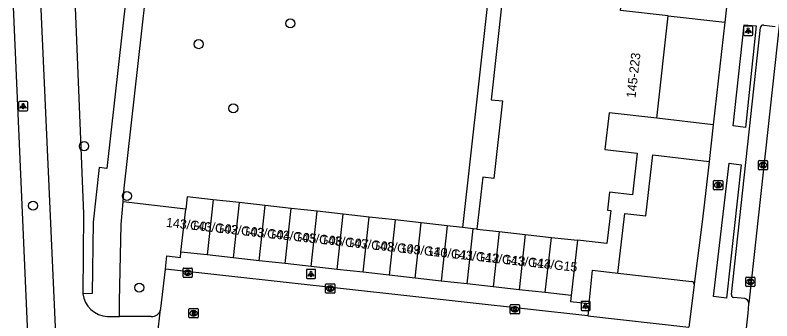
# Model space of a CAD drawing. Extents: x 161928 to 163055, y 386475 to 387428.
# Drawn here: x 161979 to 162060.7, y 386611.6 to 386644.6 of the extents above; entities that cross this region are included whole.
import ezdxf

# ---------------------------------------------------------------- set-up
doc = ezdxf.new("R2010")
doc.units = 0
for name, color, linetype in [('IMGEO_Boom', 7, 'Continuous'), ('IMGEO_Brandkraan', 7, 'Continuous'), ('IMGEO_Fietspad_gesloten', 7, 'Continuous'), ('IMGEO_Groenvoorziening', 7, 'Continuous'), ('IMGEO_Kolk', 7, 'Continuous'), ('IMGEO_Lichtpunt', 7, 'Continuous'), ('IMGEO_Pand', 7, 'Continuous'), ('IMGEO_Pand_nummerreeks', 7, 'Continuous'), ('IMGEO_Parkeervlak_open', 7, 'Continuous'), ('IMGEO_Rijbaan_lokaal_open', 7, 'Continuous'), ('IMGEO_Rijbaan_regionaal_gesloten', 7, 'Continuous'), ('IMGEO_Rioolput', 7, 'Continuous'), ('IMGEO_Voetpad_open', 7, 'Continuous')]:
    doc.layers.add(name, color=color, linetype=linetype)

msp = doc.modelspace()

# ---------------------------------------------------------------- linework, layer by layer
at = {"layer": 'IMGEO_Boom'}
for centre in [(162008.736, 386643.743), (161998.843, 386641.507), (162002.594, 386634.574), (161986.471, 386630.491), (161991.087, 386625.111), (161980.961, 386624.056), (161992.421, 386615.212)]:
    msp.add_circle(centre, 0.489, dxfattribs=at)
at = {"layer": 'IMGEO_Brandkraan'}
for p, q in [((162054.441, 386625.856), (162054.441, 386626.708)), ((162054.516, 386626.782), (162055.368, 386626.782)), ((162055.442, 386626.708), (162055.442, 386625.856)), ((162054.952, 386626.002), (162054.927, 386626.002)), ((162054.929, 386626.562), (162054.954, 386626.562)), ((162055.368, 386625.782), (162054.516, 386625.782))]:
    msp.add_line(p, q, dxfattribs=at)
for points in [[(162054.441, 386625.856), (162054.441, 386626.708)], [(162054.516, 386626.782), (162055.368, 386626.782)], [(162055.442, 386626.708), (162055.442, 386625.856)], [(162054.789, 386626.482), (162054.789, 386626.082), (162055.002, 386626.082)], [(162055.02, 386626.482), (162054.789, 386626.482)], [(162054.968, 386626.401), (162054.914, 386626.401), (162054.914, 386626.325)], [(162054.914, 386626.325), (162054.967, 386626.325)], [(162054.976, 386626.249), (162054.914, 386626.249), (162054.914, 386626.168)], [(162054.914, 386626.168), (162054.976, 386626.168)], [(162055.368, 386625.782), (162054.516, 386625.782)]]:
    msp.add_lwpolyline(points, dxfattribs=at)
for centre, radius, start, end in [((162054.518, 386626.706), 0.0765, 91.55205, 178.44795), ((162054.518, 386626.706), 0.0765, 91.55205, 178.44795), ((162055.366, 386626.706), 0.0765, 1.55205, 88.44795), ((162055.366, 386626.706), 0.0765, 1.55205, 88.44795), ((162054.518, 386625.858), 0.0765, 181.55205, 268.44795), ((162054.518, 386625.858), 0.0765, 181.55205, 268.44795), ((162054.969, 386626.363), 0.0379, 267.82845, 90.93552), ((162054.977, 386626.208), 0.0404, 269.87594, 90.50774), ((162055.008, 386626.333), 0.251, 268.66757, 293.53466), ((162055.024, 386626.337), 0.145, 59.4692, 91.53667), ((162055.049, 386626.384), 0.0922, 285.51372, 58.15012), ((162055.054, 386626.192), 0.105, 301.31148, 78.98903), ((162055.366, 386625.858), 0.0765, 271.55205, 358.44795), ((162055.366, 386625.858), 0.0765, 271.55205, 358.44795)]:
    msp.add_arc(centre, radius, start, end, dxfattribs=at)
for centre, major_axis, ratio, start_param, end_param in [((162054.928, 386626.282), (-0.387, 0.002), 0.722429, 4.712389, 7.853982), ((162054.953, 386626.282), (-0.39, 0.002), 0.717154, 1.570796, 4.712389)]:
    msp.add_ellipse(centre, major_axis=major_axis, ratio=ratio, start_param=start_param, end_param=end_param, dxfattribs=at)
at = {"layer": 'IMGEO_Fietspad_gesloten'}
for points in [[(161984.736, 386580.648), (161979.611, 386694.81), (161979.277, 386701.082), (161979.827, 386719.32), (161980.765, 386731.703), (161982.714, 386750), (161987.259, 386790.761)], [(161982.763, 386700.414), (161982.834, 386697.131), (161985.017, 386657.078), (161986.078, 386631.198), (161986.407, 386623.174), (161986.323, 386614.553)], [(161988.988, 386612.104), (161990.289, 386612.098)], [(161993.706, 386612.082), (161990.289, 386612.098)]]:
    msp.add_lwpolyline(points, dxfattribs=at)
for centre, radius, start, end in [((161989.121, 386614.923), 2.822, 187.53195, 267.30518), ((161993.734, 386613.113), 1.032, 268.45682, 346.01003)]:
    msp.add_arc(centre, radius, start, end, dxfattribs=at)
at = {"layer": 'IMGEO_Groenvoorziening'}
for points in [[(162031.664, 386660.431), (162027.344, 386621.709)], [(161997.447, 386623.691), (161990.684, 386624.497)]]:
    msp.add_lwpolyline(points, dxfattribs=at)
at = {"layer": 'IMGEO_Kolk'}
for p, q in [((162059.295, 386628.019), (162059.295, 386628.871)), ((162059.37, 386628.945), (162060.222, 386628.945)), ((162059.783, 386628.725), (162059.808, 386628.725)), ((162060.296, 386628.871), (162060.296, 386628.019)), ((162060.222, 386627.945), (162059.37, 386627.945)), ((162059.806, 386628.165), (162059.781, 386628.165)), ((161997.151, 386616.4), (161997.151, 386617.252)), ((161997.226, 386617.326), (161998.078, 386617.326)), ((161997.639, 386617.106), (161997.664, 386617.106)), ((161998.152, 386617.252), (161998.152, 386616.4)), ((161998.078, 386616.326), (161997.226, 386616.326)), ((161997.662, 386616.546), (161997.637, 386616.546)), ((162057.925, 386615.421), (162057.925, 386616.273)), ((162058, 386616.347), (162058.852, 386616.347)), ((162058.413, 386616.127), (162058.438, 386616.127)), ((162058.926, 386616.273), (162058.926, 386615.421)), ((162012.552, 386614.691), (162012.552, 386615.543)), ((162012.627, 386615.617), (162013.479, 386615.617)), ((162013.04, 386615.397), (162013.065, 386615.397)), ((162013.553, 386615.543), (162013.553, 386614.691)), ((162058.852, 386615.347), (162058, 386615.347)), ((162058.436, 386615.567), (162058.411, 386615.567)), ((162013.479, 386614.617), (162012.627, 386614.617)), ((162013.063, 386614.837), (162013.038, 386614.837)), ((162032.49, 386612.452), (162032.49, 386613.304)), ((162032.565, 386613.378), (162033.417, 386613.378)), ((162032.978, 386613.158), (162033.003, 386613.158)), ((162033.491, 386613.304), (162033.491, 386612.452)), ((162033.417, 386612.378), (162032.565, 386612.378)), ((162033.001, 386612.598), (162032.976, 386612.598))]:
    msp.add_line(p, q, dxfattribs=at)
for points in [[(162059.295, 386628.019), (162059.295, 386628.871)], [(162059.37, 386628.945), (162060.222, 386628.945)], [(162059.616, 386628.645), (162059.739, 386628.645), (162059.739, 386628.494), (162059.869, 386628.645), (162060.033, 386628.645), (162059.887, 386628.494), (162060.04, 386628.245), (162059.888, 386628.245), (162059.803, 386628.409), (162059.739, 386628.342), (162059.739, 386628.245), (162059.616, 386628.245), (162059.616, 386628.645)], [(162060.296, 386628.871), (162060.296, 386628.019)], [(162060.222, 386627.945), (162059.37, 386627.945)], [(161997.151, 386616.4), (161997.151, 386617.252)], [(161997.226, 386617.326), (161998.078, 386617.326)], [(161997.472, 386617.026), (161997.595, 386617.026), (161997.595, 386616.875), (161997.725, 386617.026), (161997.889, 386617.026), (161997.743, 386616.875), (161997.896, 386616.626), (161997.744, 386616.626), (161997.659, 386616.79), (161997.595, 386616.723), (161997.595, 386616.626), (161997.472, 386616.626), (161997.472, 386617.026)], [(161998.152, 386617.252), (161998.152, 386616.4)], [(161998.078, 386616.326), (161997.226, 386616.326)], [(162057.925, 386615.421), (162057.925, 386616.273)], [(162058, 386616.347), (162058.852, 386616.347)], [(162058.246, 386616.047), (162058.369, 386616.047), (162058.369, 386615.896), (162058.499, 386616.047), (162058.663, 386616.047), (162058.517, 386615.896), (162058.67, 386615.647), (162058.518, 386615.647), (162058.433, 386615.811), (162058.369, 386615.744), (162058.369, 386615.647), (162058.246, 386615.647), (162058.246, 386616.047)], [(162058.926, 386616.273), (162058.926, 386615.421)], [(162012.552, 386614.691), (162012.552, 386615.543)], [(162012.627, 386615.617), (162013.479, 386615.617)], [(162012.873, 386615.317), (162012.996, 386615.317), (162012.996, 386615.166), (162013.126, 386615.317), (162013.29, 386615.317), (162013.144, 386615.166), (162013.297, 386614.917), (162013.145, 386614.917), (162013.06, 386615.081), (162012.996, 386615.014), (162012.996, 386614.917), (162012.873, 386614.917), (162012.873, 386615.317)], [(162013.553, 386615.543), (162013.553, 386614.691)], [(162058.852, 386615.347), (162058, 386615.347)], [(162013.479, 386614.617), (162012.627, 386614.617)], [(162032.49, 386612.452), (162032.49, 386613.304)], [(162032.565, 386613.378), (162033.417, 386613.378)], [(162032.811, 386613.078), (162032.934, 386613.078), (162032.934, 386612.927), (162033.064, 386613.078), (162033.228, 386613.078), (162033.082, 386612.927), (162033.235, 386612.678), (162033.083, 386612.678), (162032.998, 386612.842), (162032.934, 386612.775), (162032.934, 386612.678), (162032.811, 386612.678), (162032.811, 386613.078)], [(162033.491, 386613.304), (162033.491, 386612.452)], [(162033.417, 386612.378), (162032.565, 386612.378)]]:
    msp.add_lwpolyline(points, dxfattribs=at)
for centre, start, end in [((162059.372, 386628.869), 91.55205, 178.44795), ((162059.372, 386628.869), 91.55205, 178.44795), ((162060.22, 386628.869), 1.55205, 88.44795), ((162060.22, 386628.869), 1.55205, 88.44795), ((162059.372, 386628.021), 181.55205, 268.44795), ((162059.372, 386628.021), 181.55205, 268.44795), ((162060.22, 386628.021), 271.55205, 358.44795), ((162060.22, 386628.021), 271.55205, 358.44795), ((161997.228, 386617.25), 91.55205, 178.44795), ((161997.228, 386617.25), 91.55205, 178.44795), ((161998.076, 386617.25), 1.55205, 88.44795), ((161998.076, 386617.25), 1.55205, 88.44795), ((161997.228, 386616.402), 181.55205, 268.44795), ((161997.228, 386616.402), 181.55205, 268.44795), ((161998.076, 386616.402), 271.55205, 358.44795), ((161998.076, 386616.402), 271.55205, 358.44795), ((162058.002, 386616.271), 91.55205, 178.44795), ((162058.002, 386616.271), 91.55205, 178.44795), ((162058.85, 386616.271), 1.55205, 88.44795), ((162058.85, 386616.271), 1.55205, 88.44795), ((162012.629, 386615.541), 91.55205, 178.44795), ((162012.629, 386615.541), 91.55205, 178.44795), ((162013.477, 386615.541), 1.55205, 88.44795), ((162013.477, 386615.541), 1.55205, 88.44795), ((162058.002, 386615.423), 181.55205, 268.44795), ((162058.002, 386615.423), 181.55205, 268.44795), ((162058.85, 386615.423), 271.55205, 358.44795), ((162058.85, 386615.423), 271.55205, 358.44795), ((162012.629, 386614.693), 181.55205, 268.44795), ((162012.629, 386614.693), 181.55205, 268.44795), ((162013.477, 386614.693), 271.55205, 358.44795), ((162013.477, 386614.693), 271.55205, 358.44795), ((162032.567, 386613.302), 91.55205, 178.44795), ((162032.567, 386613.302), 91.55205, 178.44795), ((162033.415, 386613.302), 1.55205, 88.44795), ((162033.415, 386613.302), 1.55205, 88.44795), ((162032.567, 386612.454), 181.55205, 268.44795), ((162032.567, 386612.454), 181.55205, 268.44795), ((162033.415, 386612.454), 271.55205, 358.44795), ((162033.415, 386612.454), 271.55205, 358.44795)]:
    msp.add_arc(centre, 0.0765, start, end, dxfattribs=at)
for centre, major_axis, ratio, start_param, end_param in [((162059.782, 386628.445), (-0.387, 0.002), 0.722429, 4.712389, 7.853982), ((162059.807, 386628.445), (-0.39, 0.002), 0.717154, 1.570796, 4.712389), ((161997.638, 386616.826), (-0.387, 0.002), 0.722429, 4.712389, 7.853982), ((161997.663, 386616.826), (-0.39, 0.002), 0.717154, 1.570796, 4.712389), ((162058.412, 386615.847), (-0.387, 0.002), 0.722429, 4.712389, 7.853982), ((162058.437, 386615.847), (-0.39, 0.002), 0.717154, 1.570796, 4.712389), ((162013.039, 386615.117), (-0.387, 0.002), 0.722429, 4.712389, 7.853982), ((162013.064, 386615.117), (-0.39, 0.002), 0.717154, 1.570796, 4.712389), ((162032.977, 386612.878), (-0.387, 0.002), 0.722429, 4.712389, 7.853982), ((162033.002, 386612.878), (-0.39, 0.002), 0.717154, 1.570796, 4.712389)]:
    msp.add_ellipse(centre, major_axis=major_axis, ratio=ratio, start_param=start_param, end_param=end_param, dxfattribs=at)
at = {"layer": 'IMGEO_Lichtpunt'}
for p, q in [((162057.7, 386643.356), (162057.7, 386642.549)), ((162057.7, 386643.356), (162057.7, 386642.549)), ((162058.602, 386643.451), (162057.794, 386643.451)), ((162058.602, 386643.451), (162057.794, 386643.451)), ((162058.696, 386642.549), (162058.696, 386643.356)), ((162058.696, 386642.549), (162058.696, 386643.356)), ((162057.794, 386642.455), (162058.602, 386642.455)), ((162057.794, 386642.455), (162058.602, 386642.455)), ((161979.385, 386635.216), (161979.385, 386634.409)), ((161979.385, 386635.216), (161979.385, 386634.409)), ((161980.287, 386635.311), (161979.479, 386635.311)), ((161980.287, 386635.311), (161979.479, 386635.311)), ((161980.381, 386634.409), (161980.381, 386635.216)), ((161980.381, 386634.409), (161980.381, 386635.216)), ((161979.479, 386634.315), (161980.287, 386634.315)), ((161979.479, 386634.315), (161980.287, 386634.315)), ((162010.476, 386617.095), (162010.476, 386616.288)), ((162010.476, 386617.095), (162010.476, 386616.288)), ((162011.378, 386617.19), (162010.57, 386617.19)), ((162011.378, 386617.19), (162010.57, 386617.19)), ((162011.472, 386616.288), (162011.472, 386617.095)), ((162011.472, 386616.288), (162011.472, 386617.095)), ((162010.57, 386616.194), (162011.378, 386616.194)), ((162010.57, 386616.194), (162011.378, 386616.194)), ((162040.138, 386613.641), (162040.138, 386612.834)), ((162040.138, 386613.641), (162040.138, 386612.834)), ((162041.04, 386613.736), (162040.232, 386613.736)), ((162041.04, 386613.736), (162040.232, 386613.736)), ((162041.134, 386612.834), (162041.134, 386613.641)), ((162041.134, 386612.834), (162041.134, 386613.641)), ((162040.232, 386612.74), (162041.04, 386612.74)), ((162040.232, 386612.74), (162041.04, 386612.74))]:
    msp.add_line(p, q, dxfattribs=at)
for points in [[(162058.074, 386643.02), (162058.113, 386642.992), (162057.925, 386642.73), (162057.887, 386642.757), (162058.074, 386643.02)], [(162058.286, 386642.992), (162058.324, 386643.019), (162058.511, 386642.757), (162058.472, 386642.729), (162058.286, 386642.992)], [(162058.176, 386642.972), (162058.223, 386642.972), (162058.223, 386642.65), (162058.176, 386642.65), (162058.176, 386642.972)], [(161979.759, 386634.88), (161979.798, 386634.852), (161979.61, 386634.59), (161979.572, 386634.617), (161979.759, 386634.88)], [(161979.971, 386634.852), (161980.009, 386634.879), (161980.196, 386634.617), (161980.157, 386634.589), (161979.971, 386634.852)], [(161979.861, 386634.832), (161979.908, 386634.832), (161979.908, 386634.51), (161979.861, 386634.51), (161979.861, 386634.832)], [(162010.85, 386616.759), (162010.889, 386616.731), (162010.701, 386616.469), (162010.663, 386616.496), (162010.85, 386616.759)], [(162010.952, 386616.711), (162010.999, 386616.711), (162010.999, 386616.389), (162010.952, 386616.389), (162010.952, 386616.711)], [(162011.062, 386616.731), (162011.1, 386616.758), (162011.287, 386616.496), (162011.248, 386616.468), (162011.062, 386616.731)], [(162040.512, 386613.305), (162040.551, 386613.277), (162040.363, 386613.015), (162040.325, 386613.042), (162040.512, 386613.305)], [(162040.614, 386613.257), (162040.661, 386613.257), (162040.661, 386612.935), (162040.614, 386612.935), (162040.614, 386613.257)], [(162040.724, 386613.277), (162040.762, 386613.304), (162040.949, 386613.042), (162040.91, 386613.014), (162040.724, 386613.277)]]:
    msp.add_lwpolyline(points, dxfattribs=at)
for centre in [(162058.199, 386643.154), (161979.884, 386635.014), (162010.975, 386616.893), (162040.637, 386613.439)]:
    msp.add_circle(centre, 0.0994, dxfattribs=at)
for centre, start, end in [((162057.794, 386643.356), 90, 180), ((162057.794, 386643.356), 90, 180), ((162058.602, 386643.356), 0, 90), ((162058.602, 386643.356), 0, 90), ((162057.794, 386642.549), 180, 270), ((162057.794, 386642.549), 180, 270), ((162058.602, 386642.549), 270, 0), ((162058.602, 386642.549), 270, 360), ((161979.479, 386635.216), 90, 180), ((161979.479, 386635.216), 90, 180), ((161980.287, 386635.216), 0, 90), ((161980.287, 386635.216), 0, 90), ((161979.479, 386634.409), 180, 270), ((161979.479, 386634.409), 180, 270), ((161980.287, 386634.409), 270, 0), ((161980.287, 386634.409), 270, 360), ((162010.57, 386617.095), 90, 180), ((162010.57, 386617.095), 90, 180), ((162011.378, 386617.095), 0, 90), ((162011.378, 386617.095), 0, 90), ((162010.57, 386616.288), 180, 270), ((162010.57, 386616.288), 180, 270), ((162011.378, 386616.288), 270, 0), ((162011.378, 386616.288), 270, 360), ((162040.232, 386613.641), 90, 180), ((162040.232, 386613.641), 90, 180), ((162041.04, 386613.641), 0, 90), ((162041.04, 386613.641), 0, 90), ((162040.232, 386612.834), 180, 270), ((162040.232, 386612.834), 180, 270), ((162041.04, 386612.834), 270, 0), ((162041.04, 386612.834), 270, 360)]:
    msp.add_arc(centre, 0.0946, start, end, dxfattribs=at)
at = {"layer": 'IMGEO_Pand'}
for points in [[(162033.207, 386660.295), (162032.572, 386654.589), (162033.788, 386654.454), (162032.858, 386646.103), (162031.616, 386646.242), (162030.421, 386635.511), (162031.659, 386635.373), (162030.727, 386626.999), (162029.524, 386627.133), (162028.901, 386621.536)], [(162049.548, 386644.556), (162044.41, 386645.129), (162044.816, 386649.034), (162048.304, 386648.645)], [(162048.319, 386633.515), (162049.548, 386644.556)], [(162048.319, 386633.515), (162043.181, 386634.087), (162042.701, 386630.128), (162046.189, 386629.74), (162045.689, 386625.252), (162043.226, 386625.526), (162043.011, 386623.597), (162043.342, 386623.56), (162042.942, 386619.973), (162039.742, 386620.33)], [(162000.405, 386624.708), (161997.595, 386625.021), (161997.447, 386623.691)], [(162000.405, 386624.708), (161999.742, 386618.745)], [(162003.215, 386624.395), (162000.405, 386624.708)], [(162003.215, 386624.395), (162002.552, 386618.433)], [(162006.025, 386624.083), (162003.215, 386624.395)], [(161996.932, 386619.058), (161997.447, 386623.691)], [(162005.361, 386618.12), (162006.025, 386624.083)], [(162008.835, 386623.77), (162006.025, 386624.083)], [(162008.171, 386617.807), (162008.835, 386623.77)], [(162011.645, 386623.457), (162008.835, 386623.77)], [(162010.981, 386617.494), (162011.645, 386623.457)], [(162014.454, 386623.144), (162011.645, 386623.457)], [(162013.791, 386617.182), (162014.454, 386623.144)], [(162017.264, 386622.831), (162014.454, 386623.144)], [(162016.601, 386616.869), (162017.264, 386622.831)], [(162020.074, 386622.519), (162017.264, 386622.831)], [(162020.074, 386622.519), (162019.41, 386616.556)], [(162022.884, 386622.206), (162020.074, 386622.519)], [(162022.22, 386616.243), (162022.884, 386622.206)], [(162025.694, 386621.893), (162022.884, 386622.206)], [(162025.694, 386621.893), (162025.03, 386615.931)], [(162027.344, 386621.709), (162025.694, 386621.893)], [(162028.503, 386621.58), (162027.344, 386621.709)], [(162027.84, 386615.618), (162028.503, 386621.58)], [(162028.901, 386621.536), (162028.503, 386621.58)], [(162028.901, 386621.536), (162031.313, 386621.268)], [(162031.313, 386621.268), (162030.65, 386615.305)], [(162031.313, 386621.268), (162034.123, 386620.955)], [(162034.123, 386620.955), (162033.459, 386614.992)], [(162034.123, 386620.955), (162036.933, 386620.643)], [(162036.269, 386614.68), (162036.933, 386620.643)], [(162036.933, 386620.643), (162039.742, 386620.33)], [(162039.742, 386620.33), (162039.079, 386614.367)], [(161999.742, 386618.745), (161996.932, 386619.058)], [(162002.552, 386618.433), (161999.742, 386618.745)], [(162005.361, 386618.12), (162002.552, 386618.433)], [(162008.171, 386617.807), (162005.361, 386618.12)], [(162010.981, 386617.494), (162008.171, 386617.807)], [(162013.791, 386617.182), (162010.981, 386617.494)], [(162016.601, 386616.869), (162013.791, 386617.182)], [(162019.41, 386616.556), (162016.601, 386616.869)], [(162022.22, 386616.243), (162019.41, 386616.556)], [(162025.03, 386615.931), (162022.22, 386616.243)], [(162027.84, 386615.618), (162025.03, 386615.931)], [(162030.65, 386615.305), (162027.84, 386615.618)], [(162033.459, 386614.992), (162030.65, 386615.305)], [(162036.269, 386614.68), (162033.459, 386614.992)], [(162039.079, 386614.367), (162036.269, 386614.68)]]:
    msp.add_lwpolyline(points, dxfattribs=at)
at = {"layer": 'IMGEO_Parkeervlak_open'}
msp.add_lwpolyline([(162044.129, 386616.787), (162052.113, 386615.893)], dxfattribs=at)
msp.add_arc((162052.072, 386615.619), 0.277, 356.71692, 81.56, dxfattribs=at)
at = {"layer": 'IMGEO_Rijbaan_lokaal_open'}
for points in [[(162061.585, 386643.805), (162058.246, 386613.543)], [(161994.754, 386612.959), (161995.25, 386617.216)], [(162040.86, 386612.186), (161995.25, 386617.216)], [(161994.297, 386609.109), (161994.735, 386612.864)], [(162058.246, 386613.543), (162058.239, 386613.473), (162058.171, 386612.457), (162056.936, 386601.481), (162056.523, 386597.775), (162056.212, 386594.954)], [(162040.86, 386612.186), (162051.78, 386610.944)]]:
    msp.add_lwpolyline(points, dxfattribs=at)
msp.add_arc((161994.012, 386613.058), 0.749, 344.97984, 352.4003, dxfattribs=at)
at = {"layer": 'IMGEO_Rijbaan_regionaal_gesloten'}
msp.add_lwpolyline([(161981.679, 386580.648), (161976.551, 386697.302), (161974.502, 386742.455), (161974.558, 386746.864), (161974.908, 386750), (161979.57, 386791.732)], dxfattribs=at)
at = {"layer": 'IMGEO_Rioolput'}
for p, q in [((161997.792, 386612.03), (161997.792, 386612.882)), ((161997.867, 386612.956), (161998.719, 386612.956)), ((161998.793, 386612.882), (161998.793, 386612.03)), ((161998.303, 386612.176), (161998.278, 386612.176)), ((161998.28, 386612.736), (161998.305, 386612.736)), ((161998.719, 386611.956), (161997.867, 386611.956))]:
    msp.add_line(p, q, dxfattribs=at)
for points in [[(161997.792, 386612.03), (161997.792, 386612.882)], [(161997.867, 386612.956), (161998.719, 386612.956)], [(161998.793, 386612.882), (161998.793, 386612.03)], [(161998.381, 386612.654), (161998.129, 386612.656), (161998.129, 386612.256)], [(161998.129, 386612.256), (161998.253, 386612.256), (161998.253, 386612.418), (161998.264, 386612.418)], [(161998.307, 386612.575), (161998.253, 386612.575), (161998.253, 386612.494)], [(161998.253, 386612.494), (161998.305, 386612.494)], [(161998.311, 386612.389), (161998.382, 386612.256), (161998.522, 386612.256), (161998.457, 386612.382)], [(161998.719, 386611.956), (161997.867, 386611.956)]]:
    msp.add_lwpolyline(points, dxfattribs=at)
for centre, radius, start, end in [((161997.869, 386612.88), 0.0765, 91.55205, 178.44795), ((161997.869, 386612.88), 0.0765, 91.55205, 178.44795), ((161998.717, 386612.88), 0.0765, 1.55205, 88.44795), ((161998.717, 386612.88), 0.0765, 1.55205, 88.44795), ((161997.869, 386612.032), 0.0765, 181.55205, 268.44795), ((161997.869, 386612.032), 0.0765, 181.55205, 268.44795), ((161998.263, 386612.365), 0.0533, 26.02933, 88.69889), ((161998.289, 386612.683), 0.19, 274.7715, 282.96867), ((161998.313, 386612.479), 0.0964, 77.00612, 93.18647), ((161998.327, 386612.536), 0.0378, 276.66336, 79.67722), ((161998.38, 386612.544), 0.109, 350.36119, 89.41601), ((161998.378, 386612.544), 0.112, 277.58423, 350.98172), ((161998.362, 386612.329), 0.108, 29.51342, 73.79051), ((161998.717, 386612.032), 0.0765, 271.55205, 358.44795), ((161998.717, 386612.032), 0.0765, 271.55205, 358.44795)]:
    msp.add_arc(centre, radius, start, end, dxfattribs=at)
for centre, major_axis, ratio, start_param, end_param in [((161998.279, 386612.456), (-0.387, 0.002), 0.722429, 4.712389, 7.853982), ((161998.304, 386612.456), (-0.39, 0.002), 0.717154, 1.570796, 4.712389)]:
    msp.add_ellipse(centre, major_axis=major_axis, ratio=ratio, start_param=start_param, end_param=end_param, dxfattribs=at)
at = {"layer": 'IMGEO_Voetpad_open'}
for points in [[(161990.684, 386624.497), (161990.807, 386625.964), (161995.016, 386663.48)], [(161991.413, 386650.255), (161988.931, 386628.093), (161988.105, 386628.184), (161987.456, 386622.282), (161987.333, 386614.588), (161986.323, 386614.553)], [(162056.103, 386647.755), (162055.675, 386643.889)], [(162049.548, 386644.556), (162055.675, 386643.889)], [(162055.675, 386643.889), (162054.418, 386632.792)], [(162056.373, 386614.458), (162059.525, 386643.311)], [(162057.771, 386643.609), (162059.069, 386643.47), (162057.885, 386632.522), (162056.572, 386632.689), (162057.771, 386643.609)], [(162059.866, 386643.546), (162061.094, 386643.411)], [(162054.418, 386632.792), (162048.319, 386633.515)], [(162054.418, 386632.792), (162053.971, 386628.851)], [(162044.129, 386616.787), (162044.853, 386623.209), (162047.145, 386622.964), (162047.877, 386629.547), (162053.971, 386628.851)], [(162053.971, 386628.851), (162053.483, 386624.455), (162053.217, 386622.316), (162052.349, 386615.603)], [(162057.445, 386628.464), (162055.867, 386614.072), (162054.463, 386614.25), (162056.126, 386628.64), (162057.445, 386628.464)], [(161990.289, 386612.098), (161990.276, 386613.736), (161990.478, 386622.045), (161990.684, 386624.497)], [(161995.25, 386617.216), (161995.39, 386618.643), (161996.871, 386618.476), (161996.932, 386619.058)], [(162041, 386613.497), (162041.384, 386617.095), (162044.129, 386616.787)], [(162052.349, 386615.603), (162052.344, 386615.562), (162051.809, 386611.197), (162051.78, 386610.944)], [(162039.079, 386614.367), (162039.014, 386613.721), (162041, 386613.497)], [(162057.814, 386614.026), (162056.609, 386614.163)], [(162041, 386613.497), (162040.86, 386612.186)]]:
    msp.add_lwpolyline(points, dxfattribs=at)
for centre, radius, start, end in [((162059.805, 386643.27), 0.283, 77.45038, 171.69493), ((162056.654, 386614.441), 0.282, 176.57897, 260.74064), ((162057.78, 386613.561), 0.466, 357.75189, 85.86764)]:
    msp.add_arc(centre, radius, start, end, dxfattribs=at)

# ---------------------------------------------------------------- texts
at = {"layer": 'IMGEO_Pand_nummerreeks'}
for s, rotation, p in [('145-223', 83.64842, (162046.021, 386635.647)), ('143/G01', 353.74741, (161995.282, 386621.783)), ('143/G02', 353.74741, (161997.975, 386621.488)), ('143/G03', 353.74741, (162000.79, 386621.18)), ('143/G04', 353.74741, (162003.599, 386620.872)), ('143/G05', 353.74741, (162006.408, 386620.564)), ('143/G06', 353.74741, (162009.216, 386620.257)), ('143/G07', 353.74741, (162012.025, 386619.949)), ('143/G08', 353.74741, (162014.837, 386619.641)), ('143/G09', 353.74741, (162017.64, 386619.334)), ('143/G10', 353.74741, (162020.545, 386619.015)), ('143/G11', 353.74741, (162023.461, 386618.696)), ('143/G12', 353.74741, (162026.154, 386618.401)), ('143/G13', 353.74741, (162028.969, 386618.092)), ('143/G14', 353.74741, (162031.777, 386617.785)), ('143/G15', 353.74741, (162034.586, 386617.477))]:
    msp.add_text(s, height=1, rotation=rotation, dxfattribs=at).set_placement(p)

doc.saveas('drawing.dxf')
